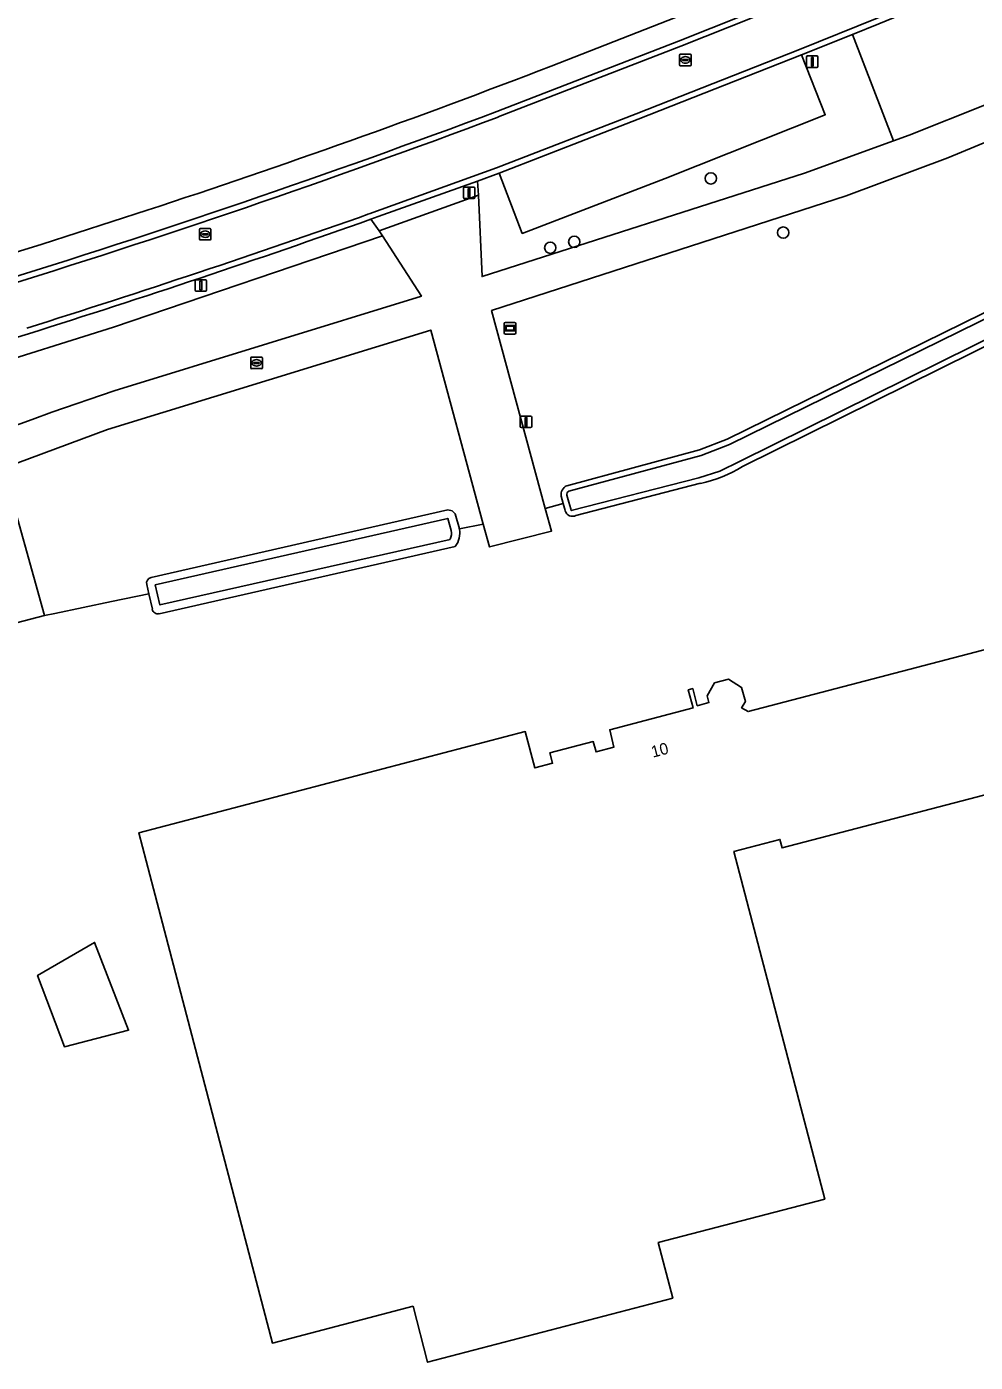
# Model space of a CAD drawing. Extents: x 162879 to 165540, y 384011 to 385181.
# Drawn here: x 163278.2 to 163360.1, y 384254.7 to 384370.1 of the extents above; entities that cross this region are included whole.
import ezdxf

# ---------------------------------------------------------------- set-up
doc = ezdxf.new("R2010")
doc.units = 0
for name, color, linetype in [('IMGEO_Boom', 7, 'Continuous'), ('IMGEO_Brandkraan', 7, 'Continuous'), ('IMGEO_Erf', 7, 'Continuous'), ('IMGEO_Gemengd_bos', 7, 'Continuous'), ('IMGEO_Groenvoorziening', 7, 'Continuous'), ('IMGEO_Lichtmast', 7, 'Continuous'), ('IMGEO_Loofbos', 7, 'Continuous'), ('IMGEO_Oever', 7, 'Continuous'), ('IMGEO_Pand', 7, 'Continuous'), ('IMGEO_Pand_nummerreeks', 7, 'Continuous'), ('IMGEO_Parkeervlak_open', 7, 'Continuous'), ('IMGEO_Reclamebord', 7, 'Continuous'), ('IMGEO_Rijbaan_lokaal_open', 7, 'Continuous'), ('IMGEO_Rioolput', 7, 'Continuous'), ('IMGEO_Voetpad_open', 7, 'Continuous'), ('IMGEO_Waterloop', 7, 'Continuous')]:
    doc.layers.add(name, color=color, linetype=linetype)

msp = doc.modelspace()

# ---------------------------------------------------------------- linework, layer by layer
at = {"layer": 'IMGEO_Boom'}
for centre in [(163337.27, 384356.97), (163343.52, 384352.29), (163323.4, 384350.98), (163325.48, 384351.49)]:
    msp.add_circle(centre, 0.489, dxfattribs=at)
at = {"layer": 'IMGEO_Brandkraan'}
for p, q in [((163297.54, 384340.61), (163297.54, 384341.46)), ((163297.61, 384341.54), (163298.46, 384341.54)), ((163297.79, 384341.03), (163297.79, 384341.04)), ((163298.23, 384340.99), (163297.83, 384340.99)), ((163297.84, 384341.08), (163298.23, 384341.08)), ((163298.02, 384341.32), (163298.05, 384341.32)), ((163298.28, 384341.04), (163298.28, 384341.03)), ((163298.54, 384341.46), (163298.54, 384340.61)), ((163298.46, 384340.54), (163297.61, 384340.54)), ((163298.05, 384340.76), (163298.02, 384340.76))]:
    msp.add_line(p, q, dxfattribs=at)
for points in [[(163297.54, 384340.61), (163297.54, 384341.46)], [(163297.61, 384341.54), (163298.46, 384341.54)], [(163298.54, 384341.46), (163298.54, 384340.61)], [(163298.46, 384340.54), (163297.61, 384340.54)]]:
    msp.add_lwpolyline(points, dxfattribs=at)
for centre, radius, start, end in [((163297.61, 384341.46), 0.0765, 91.552, 178.448), ((163297.61, 384341.46), 0.0765, 91.552, 178.448), ((163297.83, 384341.04), 0.0403, 85.8775, 175.7526), ((163297.83, 384341.03), 0.0366, 178.938, 274.7102), ((163298.24, 384341.04), 0.0386, 1.7309, 96.639), ((163298.24, 384341.04), 0.043, 264.8664, 352.4533), ((163298.46, 384341.46), 0.0765, 1.552, 88.448), ((163298.46, 384341.46), 0.0765, 1.552, 88.448), ((163297.61, 384340.61), 0.0765, 181.552, 268.448), ((163297.61, 384340.61), 0.0765, 181.552, 268.448), ((163298.46, 384340.61), 0.0765, 271.552, 358.448), ((163298.46, 384340.61), 0.0765, 271.552, 358.448)]:
    msp.add_arc(centre, radius, start, end, dxfattribs=at)
for centre, major_axis, ratio, start_param, end_param in [((163298.02, 384341.04), (-0.387, 0.002), 0.722429, 4.712389, 7.853982), ((163298.05, 384341.04), (-0.39, 0.002), 0.717154, 1.570796, 4.712389)]:
    msp.add_ellipse(centre, major_axis=major_axis, ratio=ratio, start_param=start_param, end_param=end_param, dxfattribs=at)
at = {"layer": 'IMGEO_Erf'}
for points in [[(163387.48, 384348.12), (163385.55, 384354.62), (163340.01, 384332.09)], [(163336.37, 384330.64), (163325.62, 384327.87)], [(163324.69, 384328.28), (163324.52, 384328.89), (163322.97, 384328.45), (163323.51, 384326.5), (163318.15, 384325.15), (163317.61, 384327.12), (163315.55, 384326.72)], [(163315.2, 384325.17), (163289.64, 384319.38)], [(163384.65, 384309.94), (163343.43, 384299.16), (163343.24, 384299.89), (163339.26, 384298.85), (163347.11, 384268.83), (163332.73, 384265.07), (163333.98, 384260.28), (163312.81, 384254.74), (163311.55, 384259.57), (163299.4, 384256.4), (163289.14, 384295.63), (163287.87, 384300.47), (163321.24, 384309.2), (163322.06, 384306.06), (163323.6, 384306.47), (163323.37, 384307.36), (163327.12, 384308.34), (163327.36, 384307.45), (163328.89, 384307.85), (163328.54, 384309.36), (163335.73, 384311.24), (163335.32, 384312.81), (163335.71, 384312.91), (163336.09, 384311.43), (163337.11, 384311.7), (163336.96, 384312.28), (163337.59, 384313.4), (163338.8, 384313.72), (163339.93, 384313.02), (163340.25, 384311.8), (163339.93, 384311.26), (163340.48, 384310.93), (163381.58, 384321.68)], [(163289.04, 384319.76), (163288.74, 384321.09), (163285.5, 384320.42), (163280.63, 384319.41), (163279.72, 384319.22), (163275.41, 384318.09)]]:
    msp.add_lwpolyline(points, dxfattribs=at)
msp.add_lwpolyline([(163286.98, 384283.41), (163281.44, 384281.98), (163279.12, 384288.15), (163284.05, 384290.99)], close=True, dxfattribs=at)
for centre, radius, start, end in [((163333.84, 384342.23), 11.87, 282.3092, 301.3153), ((163325.31, 384328.43), 0.641, 194.2211, 299.056), ((163313.74, 384326.32), 1.85, 321.8286, 12.534), ((163289.52, 384319.87), 0.499, 192.6308, 282.9117)]:
    msp.add_arc(centre, radius, start, end, dxfattribs=at)
at = {"layer": 'IMGEO_Gemengd_bos'}
msp.add_lwpolyline([(163288.93, 384322.51), (163314.56, 384328.34), (163314.92, 384328.27), (163315.18, 384328.01), (163315.55, 384326.72), (163317.61, 384327.12), (163313.08, 384343.87), (163285.16, 384335.28), (163276.18, 384331.96), (163279.72, 384319.22), (163280.63, 384319.41), (163285.5, 384320.42), (163288.74, 384321.09), (163288.55, 384321.91)], dxfattribs=at)
msp.add_arc((163289.04, 384322.02), 0.501, 102.8649, 192.6776, dxfattribs=at)
at = {"layer": 'IMGEO_Groenvoorziening'}
msp.add_lwpolyline([(163349.5, 384369.4), (163345.1, 384367.63), (163347.15, 384362.46), (163333.33, 384356.95), (163320.98, 384352.22), (163318.99, 384357.42), (163317.12, 384356.73), (163317.2, 384355.52), (163317.52, 384348.49), (163345.35, 384357.41), (163353.05, 384360.2)], close=True, dxfattribs=at)
for points in [[(163308.91, 384352), (163308.63, 384352.43), (163307.92, 384353.44)], [(163278.35, 384343.55), (163273.08, 384341.95), (163273.42, 384340.81), (163273.56, 384340.34), (163273.94, 384340.45), (163285.68, 384344.11), (163308.91, 384352)]]:
    msp.add_lwpolyline(points, dxfattribs=at)
msp.add_arc((163008.84, 385198.75), 896.66, 287.49173, 289.48394, dxfattribs=at)
at = {"layer": 'IMGEO_Lichtmast'}
for p, q in [((163345.53, 384366.64), (163345.53, 384367.44)), ((163345.53, 384367.44), (163345.53, 384366.64)), ((163345.63, 384367.54), (163346.42, 384367.54)), ((163346.42, 384367.54), (163345.63, 384367.54)), ((163346.52, 384367.44), (163346.52, 384366.64)), ((163346.52, 384366.64), (163346.52, 384367.44)), ((163346.42, 384366.54), (163345.63, 384366.54)), ((163345.63, 384366.54), (163346.42, 384366.54)), ((163315.9, 384355.32), (163315.9, 384356.12)), ((163315.9, 384356.12), (163315.9, 384355.32)), ((163316, 384356.22), (163316.79, 384356.22)), ((163316.79, 384356.22), (163316, 384356.22)), ((163316.89, 384356.12), (163316.89, 384355.32)), ((163316.89, 384355.32), (163316.89, 384356.12)), ((163316.79, 384355.22), (163316, 384355.22)), ((163316, 384355.22), (163316.79, 384355.22)), ((163292.73, 384347.32), (163292.73, 384348.12)), ((163292.73, 384348.12), (163292.73, 384347.32)), ((163292.83, 384348.22), (163293.62, 384348.22)), ((163293.62, 384348.22), (163292.83, 384348.22)), ((163293.72, 384348.12), (163293.72, 384347.32)), ((163293.72, 384347.32), (163293.72, 384348.12)), ((163293.62, 384347.22), (163292.83, 384347.22)), ((163292.83, 384347.22), (163293.62, 384347.22)), ((163320.81, 384335.55), (163320.81, 384336.35)), ((163320.81, 384336.35), (163320.81, 384335.55)), ((163320.91, 384336.45), (163321.7, 384336.45)), ((163321.7, 384336.45), (163320.91, 384336.45)), ((163321.8, 384336.35), (163321.8, 384335.55)), ((163321.8, 384335.55), (163321.8, 384336.35)), ((163321.7, 384335.45), (163320.91, 384335.45)), ((163320.91, 384335.45), (163321.7, 384335.45))]:
    msp.add_line(p, q, dxfattribs=at)
for points in [[(163345.95, 384367.42), (163346.1, 384367.42), (163346.1, 384366.67), (163345.95, 384366.67), (163345.95, 384367.42)], [(163316.32, 384356.1), (163316.47, 384356.1), (163316.47, 384355.35), (163316.32, 384355.35), (163316.32, 384356.1)], [(163293.15, 384348.1), (163293.3, 384348.1), (163293.3, 384347.35), (163293.15, 384347.35), (163293.15, 384348.1)], [(163321.23, 384336.32), (163321.38, 384336.32), (163321.38, 384335.57), (163321.23, 384335.57), (163321.23, 384336.32)]]:
    msp.add_lwpolyline(points, dxfattribs=at)
for centre, start, end in [((163345.63, 384367.44), 90, 180), ((163345.63, 384367.44), 90, 180), ((163346.42, 384367.44), 0, 90), ((163346.42, 384367.44), 360, 90), ((163345.63, 384366.64), 180, 270), ((163345.63, 384366.64), 180, 270), ((163346.42, 384366.64), 270, 0), ((163346.42, 384366.64), 270, 0), ((163316, 384356.12), 90, 180), ((163316, 384356.12), 90, 180), ((163316.79, 384356.12), 0, 90), ((163316.79, 384356.12), 360, 90), ((163316, 384355.32), 180, 270), ((163316, 384355.32), 180, 270), ((163316.79, 384355.32), 270, 0), ((163316.79, 384355.32), 270, 0), ((163292.83, 384348.12), 90, 180), ((163292.83, 384348.12), 90, 180), ((163293.62, 384348.12), 0, 90), ((163293.62, 384348.12), 360, 90), ((163292.83, 384347.32), 180, 270), ((163292.83, 384347.32), 180, 270), ((163293.62, 384347.32), 270, 0), ((163293.62, 384347.32), 270, 0), ((163320.91, 384336.35), 90, 180), ((163320.91, 384336.35), 90, 180), ((163321.7, 384336.35), 0, 90), ((163321.7, 384336.35), 360, 90), ((163320.91, 384335.55), 180, 270), ((163320.91, 384335.55), 180, 270), ((163321.7, 384335.55), 270, 0), ((163321.7, 384335.55), 270, 0)]:
    msp.add_arc(centre, 0.1, start, end, dxfattribs=at)
at = {"layer": 'IMGEO_Loofbos'}
for points in [[(163376.01, 384380.74), (163375.98, 384380.73), (163367.04, 384376.79), (163358.89, 384373.24), (163351.78, 384370.31), (163349.5, 384369.4), (163353.05, 384360.2), (163354.39, 384360.69), (163361.05, 384363.34), (163378.48, 384370.74)], [(163324.82, 384330.42), (163336.29, 384333.53), (163338.69, 384334.44), (163384.61, 384357.02), (163384.34, 384358.17), (163387.14, 384359.46), (163387.66, 384357.08), (163404.89, 384365.94), (163401.5, 384378.47), (163400.88, 384378.13), (163387.56, 384371.64), (163381.8, 384369.03), (163373.43, 384365.24), (163357.73, 384358.73), (163348.95, 384355.47), (163318.33, 384345.55), (163322.97, 384328.45), (163324.52, 384328.89), (163324.34, 384329.53)], [(163323.49, 384366.67), (163333.55, 384370.61), (163338.52, 384372.6)], [(163247.15, 384341.49), (163264.06, 384346.53), (163270.18, 384348.41), (163279.53, 384351.29), (163288.58, 384354.22)]]:
    msp.add_lwpolyline(points, dxfattribs=at)
msp.add_lwpolyline([(163312.28, 384346.8), (163308.91, 384352), (163285.68, 384344.11), (163273.94, 384340.45), (163273.56, 384340.34), (163275.19, 384334.92), (163278.65, 384336.14), (163280.35, 384336.78), (163285.73, 384338.61)], close=True, dxfattribs=at)
for centre, radius, start, end in [((163073.27, 385013.21), 693.27, 288.09398, 291.15709), ((163325.2, 384329.65), 0.862, 116.2285, 187.9534)]:
    msp.add_arc(centre, radius, start, end, dxfattribs=at)
at = {"layer": 'IMGEO_Oever'}
for points in [[(163389.93, 384348.62), (163388.41, 384353.62), (163387.66, 384357.08), (163387.14, 384359.46), (163384.34, 384358.17), (163384.61, 384357.02), (163338.69, 384334.44), (163336.29, 384333.53), (163324.82, 384330.42)], [(163325.01, 384329.96), (163336.44, 384333.05), (163338.89, 384333.98), (163385.18, 384356.74)], [(163387.98, 384348.23), (163385.86, 384355.34), (163339.79, 384332.54), (163338.06, 384331.68), (163336.24, 384331.12), (163325.22, 384328.29), (163325.17, 384328.42), (163325, 384329.02), (163324.84, 384329.61)], [(163340.01, 384332.09), (163385.55, 384354.62)], [(163325.62, 384327.87), (163336.37, 384330.64)], [(163324.34, 384329.53), (163324.52, 384328.89), (163324.69, 384328.28)], [(163315.18, 384328.01), (163314.92, 384328.27), (163314.56, 384328.34), (163288.93, 384322.51)], [(163314.76, 384325.8), (163289.69, 384320.13), (163289.29, 384321.86), (163314.55, 384327.61), (163314.85, 384326.57)], [(163315.55, 384326.72), (163315.18, 384328.01)], [(163289.64, 384319.38), (163315.2, 384325.17)], [(163288.55, 384321.91), (163288.74, 384321.09), (163289.04, 384319.76)]]:
    msp.add_lwpolyline(points, dxfattribs=at)
for centre, radius, start, end in [((163333.84, 384342.23), 11.87, 282.3092, 301.3153), ((163325.2, 384329.65), 0.862, 116.2285, 187.9534), ((163325.19, 384329.65), 0.353, 120.0491, 186.4229), ((163325.31, 384328.43), 0.641, 194.2211, 299.056), ((163313.76, 384326.32), 1.12, 332.4673, 12.9702), ((163313.74, 384326.32), 1.85, 321.8286, 12.534), ((163289.04, 384322.02), 0.501, 102.8649, 192.6776), ((163289.52, 384319.87), 0.499, 192.6308, 282.9117)]:
    msp.add_arc(centre, radius, start, end, dxfattribs=at)
at = {"layer": 'IMGEO_Pand'}
msp.add_lwpolyline([(163381.58, 384321.68), (163340.48, 384310.93), (163339.93, 384311.26), (163340.25, 384311.8), (163339.93, 384313.02), (163338.8, 384313.72), (163337.59, 384313.4), (163336.96, 384312.28), (163337.11, 384311.7), (163336.09, 384311.43), (163335.71, 384312.91), (163335.32, 384312.81), (163335.73, 384311.24), (163328.54, 384309.36), (163328.89, 384307.85), (163327.36, 384307.45), (163327.12, 384308.34), (163323.37, 384307.36), (163323.6, 384306.47), (163322.06, 384306.06), (163321.24, 384309.2), (163287.87, 384300.47), (163289.14, 384295.63), (163299.4, 384256.4), (163311.55, 384259.57), (163312.81, 384254.74), (163333.98, 384260.28), (163332.73, 384265.07), (163347.11, 384268.83), (163339.26, 384298.85), (163343.24, 384299.89), (163343.43, 384299.16), (163384.65, 384309.94)], dxfattribs=at)
msp.add_lwpolyline([(163281.44, 384281.98), (163286.98, 384283.41), (163284.05, 384290.99), (163279.12, 384288.15)], close=True, dxfattribs=at)
at = {"layer": 'IMGEO_Parkeervlak_open'}
msp.add_lwpolyline([(163347.15, 384362.46), (163345.1, 384367.63), (163331, 384362.07), (163318.99, 384357.42), (163320.98, 384352.22), (163333.33, 384356.95)], close=True, dxfattribs=at)
at = {"layer": 'IMGEO_Reclamebord'}
for p, q in [((163319.43, 384343.63), (163319.43, 384344.43)), ((163319.43, 384344.43), (163319.43, 384343.63)), ((163319.53, 384344.53), (163320.32, 384344.53)), ((163320.32, 384344.53), (163319.53, 384344.53)), ((163320.42, 384344.43), (163320.42, 384343.63)), ((163320.42, 384343.63), (163320.42, 384344.43)), ((163320.32, 384343.53), (163319.53, 384343.53)), ((163319.53, 384343.53), (163320.32, 384343.53))]:
    msp.add_line(p, q, dxfattribs=at)
for points in [[(163319.53, 384344.27), (163320.32, 384344.27), (163320.32, 384343.8), (163319.53, 384343.8), (163319.53, 384344.27)], [(163319.6, 384344.2), (163319.6, 384343.87), (163320.25, 384343.87), (163320.25, 384344.2), (163319.6, 384344.2)]]:
    msp.add_lwpolyline(points, dxfattribs=at)
for centre, start, end in [((163319.53, 384344.43), 90, 180), ((163319.53, 384344.43), 90, 180), ((163320.32, 384344.43), 0, 90), ((163320.32, 384344.43), 360, 90), ((163319.53, 384343.63), 180, 270), ((163319.53, 384343.63), 180, 270), ((163320.32, 384343.63), 270, 0), ((163320.32, 384343.63), 270, 0)]:
    msp.add_arc(centre, 0.1, start, end, dxfattribs=at)
at = {"layer": 'IMGEO_Rijbaan_lokaal_open'}
for points in [[(163376.18, 384381.37), (163366.8, 384377.27), (163358.67, 384373.7), (163351.63, 384370.79), (163344.92, 384368.1), (163330.82, 384362.53), (163318.75, 384357.88), (163307.75, 384353.91)], [(163307.92, 384353.44), (163308.55, 384353.67), (163317.12, 384356.73), (163318.99, 384357.42), (163331, 384362.07), (163345.1, 384367.63), (163349.5, 384369.4), (163351.78, 384370.31), (163358.89, 384373.24), (163367.04, 384376.79), (163375.98, 384380.73)], [(163307.75, 384353.91), (163318.75, 384357.88), (163330.82, 384362.53), (163344.92, 384368.1), (163351.63, 384370.79), (163358.67, 384373.7)], [(163342.94, 384372.19), (163334.48, 384368.83), (163318.8, 384362.75)], [(163343.09, 384371.73), (163334.68, 384368.4), (163318.91, 384362.27)], [(163318.91, 384362.27), (163334.68, 384368.4), (163343.09, 384371.73)], [(163236.08, 384330.73), (163238.4, 384331.48), (163248.63, 384334.64), (163260.69, 384338.19), (163268.75, 384340.62), (163273.08, 384341.95), (163278.35, 384343.55)]]:
    msp.add_lwpolyline(points, dxfattribs=at)
for centre, radius, start, end in [((163036.73, 385116.71), 805, 287.20602, 290.5114), ((163047.76, 385084.13), 771.11, 287.13946, 290.58789), ((163047.76, 385084.13), 771.11, 287.13946, 290.58789), ((163010.57, 385195.1), 892.15, 287.4557, 289.45722), ((163010.57, 385195.1), 892.15, 287.4557, 289.45722), ((163008.84, 385198.75), 896.66, 287.49173, 289.48394)]:
    msp.add_arc(centre, radius, start, end, dxfattribs=at)
at = {"layer": 'IMGEO_Rioolput'}
for p, q in [((163334.57, 384366.77), (163334.57, 384367.62)), ((163334.65, 384367.7), (163335.5, 384367.7)), ((163335.06, 384367.48), (163335.09, 384367.48)), ((163335.57, 384367.62), (163335.57, 384366.77)), ((163335.5, 384366.7), (163334.65, 384366.7)), ((163334.83, 384367.19), (163334.83, 384367.2)), ((163334.87, 384367.24), (163335.27, 384367.24)), ((163335.27, 384367.15), (163334.87, 384367.15)), ((163335.08, 384366.92), (163335.06, 384366.92)), ((163335.32, 384367.2), (163335.32, 384367.19)), ((163293.1, 384351.72), (163293.1, 384352.57)), ((163293.17, 384352.65), (163294.03, 384352.65)), ((163293.59, 384352.43), (163293.61, 384352.43)), ((163294.1, 384352.57), (163294.1, 384351.72)), ((163294.03, 384351.65), (163293.17, 384351.65)), ((163293.36, 384352.14), (163293.36, 384352.15)), ((163293.4, 384352.19), (163293.8, 384352.19)), ((163293.8, 384352.1), (163293.4, 384352.1)), ((163293.61, 384351.87), (163293.59, 384351.87)), ((163293.84, 384352.15), (163293.84, 384352.14))]:
    msp.add_line(p, q, dxfattribs=at)
for points in [[(163334.57, 384366.77), (163334.57, 384367.62)], [(163334.65, 384367.7), (163335.5, 384367.7)], [(163335.57, 384367.62), (163335.57, 384366.77)], [(163335.5, 384366.7), (163334.65, 384366.7)], [(163293.1, 384351.72), (163293.1, 384352.57)], [(163293.17, 384352.65), (163294.03, 384352.65)], [(163294.1, 384352.57), (163294.1, 384351.72)], [(163294.03, 384351.65), (163293.17, 384351.65)]]:
    msp.add_lwpolyline(points, dxfattribs=at)
for centre, radius, start, end in [((163334.65, 384367.62), 0.0765, 91.552, 178.448), ((163334.65, 384367.62), 0.0765, 91.552, 178.448), ((163335.5, 384367.62), 0.0765, 1.552, 88.448), ((163335.5, 384367.62), 0.0765, 1.552, 88.448), ((163334.65, 384366.77), 0.0765, 181.552, 268.448), ((163334.65, 384366.77), 0.0765, 181.552, 268.448), ((163334.87, 384367.2), 0.0403, 85.8775, 175.7526), ((163334.87, 384367.19), 0.0366, 178.938, 274.7102), ((163335.28, 384367.2), 0.0386, 1.7309, 96.639), ((163335.27, 384367.2), 0.043, 264.8664, 352.4533), ((163335.5, 384366.77), 0.0765, 271.552, 358.448), ((163335.5, 384366.77), 0.0765, 271.552, 358.448), ((163293.18, 384352.57), 0.0765, 91.552, 178.448), ((163293.18, 384352.57), 0.0765, 91.552, 178.448), ((163294.02, 384352.57), 0.0765, 1.552, 88.448), ((163294.02, 384352.57), 0.0765, 1.552, 88.448), ((163293.18, 384351.72), 0.0765, 181.552, 268.448), ((163293.18, 384351.72), 0.0765, 181.552, 268.448), ((163293.4, 384352.15), 0.0403, 85.8775, 175.7526), ((163293.4, 384352.14), 0.0366, 178.938, 274.7102), ((163293.8, 384352.15), 0.0386, 1.7309, 96.639), ((163293.8, 384352.15), 0.043, 264.8664, 352.4533), ((163294.02, 384351.72), 0.0765, 271.552, 358.448), ((163294.02, 384351.72), 0.0765, 271.552, 358.448)]:
    msp.add_arc(centre, radius, start, end, dxfattribs=at)
for centre, major_axis, ratio, start_param, end_param in [((163335.06, 384367.2), (-0.387, 0.002), 0.722429, 4.712389, 7.853982), ((163335.08, 384367.2), (-0.39, 0.002), 0.717154, 1.570796, 4.712389), ((163293.59, 384352.15), (-0.387, 0.002), 0.722429, 4.712389, 7.853982), ((163293.61, 384352.15), (-0.39, 0.002), 0.717154, 1.570796, 4.712389)]:
    msp.add_ellipse(centre, major_axis=major_axis, ratio=ratio, start_param=start_param, end_param=end_param, dxfattribs=at)
at = {"layer": 'IMGEO_Voetpad_open'}
for points in [[(163342.64, 384374.24), (163338.52, 384372.6), (163333.55, 384370.61), (163323.49, 384366.67)], [(163318.8, 384362.75), (163334.48, 384368.83), (163342.94, 384372.19)], [(163275.41, 384318.09), (163279.72, 384319.22), (163276.18, 384331.96), (163285.16, 384335.28), (163313.08, 384343.87), (163317.61, 384327.12), (163318.15, 384325.15), (163323.51, 384326.5), (163322.97, 384328.45), (163318.33, 384345.55), (163348.95, 384355.47), (163357.73, 384358.73), (163373.43, 384365.24), (163381.8, 384369.03), (163387.56, 384371.64)], [(163378.48, 384370.74), (163361.05, 384363.34), (163354.39, 384360.69), (163353.05, 384360.2), (163345.35, 384357.41), (163317.52, 384348.49), (163317.2, 384355.52), (163308.63, 384352.43), (163308.91, 384352), (163312.28, 384346.8), (163285.73, 384338.61), (163280.35, 384336.78), (163278.65, 384336.14), (163275.19, 384334.92)], [(163288.58, 384354.22), (163279.53, 384351.29), (163270.18, 384348.41), (163264.06, 384346.53), (163247.15, 384341.49)]]:
    msp.add_lwpolyline(points, dxfattribs=at)
msp.add_lwpolyline([(163317.2, 384355.52), (163317.12, 384356.73), (163308.55, 384353.67), (163307.92, 384353.44), (163308.63, 384352.43)], close=True, dxfattribs=at)
for centre, radius, start, end in [((163073.27, 385013.21), 693.27, 288.09398, 291.15709), ((163036.73, 385116.71), 805, 287.20602, 290.5114)]:
    msp.add_arc(centre, radius, start, end, dxfattribs=at)
at = {"layer": 'IMGEO_Waterloop'}
for points in [[(163389.44, 384348.51), (163387.92, 384353.5), (163387.17, 384356.98), (163386.78, 384358.75), (163384.92, 384357.89), (163385.18, 384356.74), (163338.89, 384333.98), (163336.44, 384333.05), (163325.01, 384329.96)], [(163324.84, 384329.61), (163325, 384329.02), (163325.17, 384328.42), (163325.22, 384328.29), (163336.24, 384331.12), (163338.06, 384331.68), (163339.79, 384332.54), (163385.86, 384355.34)], [(163314.85, 384326.57), (163314.55, 384327.61), (163289.29, 384321.86), (163289.69, 384320.13), (163314.76, 384325.8)]]:
    msp.add_lwpolyline(points, dxfattribs=at)
for centre, radius, start, end in [((163325.19, 384329.65), 0.353, 120.0491, 186.4229), ((163313.76, 384326.32), 1.12, 332.4673, 12.9702)]:
    msp.add_arc(centre, radius, start, end, dxfattribs=at)

# ---------------------------------------------------------------- texts
at = {"layer": 'IMGEO_Pand_nummerreeks'}
msp.add_text('10', height=1, rotation=14.662, dxfattribs=at).set_placement((163332.26, 384306.94))

doc.saveas('drawing.dxf')
